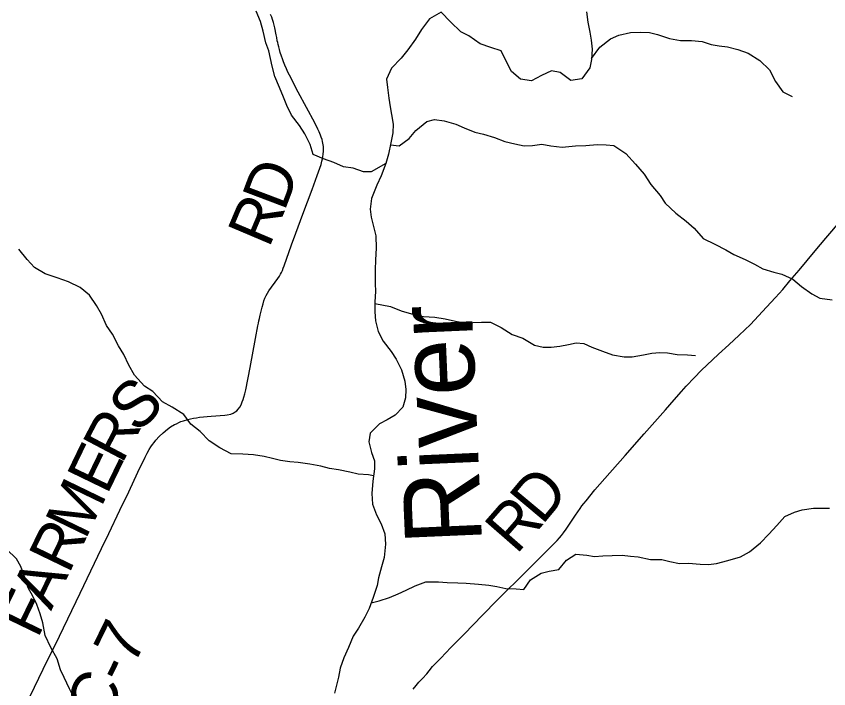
# Model space of a CAD drawing. Extents: x 0 to 1052, y -194 to 246.
# Drawn here: x 4.503 to 5.505, y 18.708 to 19.536 of the extents above; entities that cross this region are included whole.
import ezdxf

# ---------------------------------------------------------------- set-up
doc = ezdxf.new("R2010")
doc.units = 0
for name, color, linetype in [('GM_X_County_Road', 7, 'Continuous'), ('GM_X_County_Road_Text', 7, 'Continuous'), ('GM_X_County_Text', 7, 'Continuous'), ('GM_X_Major_River', 7, 'Continuous'), ('GM_X_Major_River_Text', 7, 'Continuous'), ('GM_X_Minor_River', 7, 'Continuous'), ('GM_X_Township_Road', 7, 'Continuous'), ('GM_X_Township_Road_Text', 7, 'Continuous')]:
    doc.layers.add(name, color=color, linetype=linetype)

msp = doc.modelspace()

# ---------------------------------------------------------------- linework, layer by layer
at = {"layer": 'GM_X_County_Road'}
msp.add_lwpolyline([(4.5205, 18.6985), (4.5365, 18.7315), (4.5565, 18.7722), (4.5822, 18.8253), (4.6084, 18.8803), (4.6173, 18.8987), (4.6311, 18.9273), (4.6421, 18.9502), (4.6533, 18.9744), (4.6622, 18.9929), (4.6647, 18.9976), (4.6671, 19.0022), (4.6692, 19.0054), (4.6711, 19.0083), (4.6732, 19.0109), (4.6753, 19.0136), (4.6794, 19.0181), (4.6843, 19.0228), (4.6895, 19.0271), (4.6935, 19.03), (4.6982, 19.0328), (4.7006, 19.034), (4.7037, 19.0355), (4.7063, 19.0365), (4.7094, 19.0377), (4.7147, 19.0393), (4.7179, 19.04), (4.7219, 19.0409), (4.7255, 19.0414), (4.7292, 19.042), (4.7434, 19.0433), (4.7602, 19.0444), (4.7633, 19.0448), (4.7677, 19.0459), (4.7707, 19.0471), (4.773, 19.0484), (4.775, 19.05), (4.7768, 19.0519), (4.7788, 19.0544), (4.7804, 19.0572), (4.7819, 19.0607), (4.7829, 19.0636), (4.7839, 19.0667), (4.7849, 19.0707), (4.7862, 19.0758), (4.7917, 19.1033), (4.7982, 19.1387), (4.8012, 19.1546), (4.8018, 19.1576), (4.8024, 19.1607), (4.803, 19.1637), (4.8039, 19.1676), (4.8046, 19.171), (4.8054, 19.1743), (4.8062, 19.1776), (4.8074, 19.1818), (4.8083, 19.1853), (4.8098, 19.1887), (4.8112, 19.192), (4.8129, 19.1949), (4.8146, 19.1978), (4.8258, 19.2128), (4.8276, 19.2157), (4.829, 19.2181), (4.8301, 19.2203), (4.8312, 19.2227), (4.8324, 19.2256), (4.8336, 19.2284), (4.8426, 19.2543), (4.848, 19.2688), (4.8566, 19.2921), (4.8679, 19.3223), (4.8743, 19.3398), (4.8789, 19.3534), (4.8799, 19.3572), (4.8806, 19.3601), (4.8812, 19.3632), (4.8816, 19.3657), (4.8819, 19.3701), (4.8819, 19.373), (4.8818, 19.3752), (4.8813, 19.3796), (4.8807, 19.3817), (4.8802, 19.3839), (4.8792, 19.3869), (4.8783, 19.3893), (4.8765, 19.3935), (4.8751, 19.3967), (4.8712, 19.4045), (4.8508, 19.4423), (4.8399, 19.4632), (4.8381, 19.4671), (4.8362, 19.471), (4.8343, 19.4754), (4.8326, 19.4795), (4.8313, 19.4832), (4.8301, 19.4865), (4.8287, 19.491), (4.8276, 19.4948), (4.8267, 19.4981), (4.8261, 19.5008), (4.8255, 19.5036), (4.825, 19.5056), (4.8243, 19.5096), (4.8237, 19.5129), (4.8219, 19.5215), (4.821, 19.525), (4.8202, 19.5281), (4.819, 19.5319), (4.8181, 19.5347), (4.8168, 19.5378)], dxfattribs=at)
at = {"layer": 'GM_X_Major_River'}
for points in [[(5.2059, 19.5412), (5.2075, 19.5286), (5.2103, 19.5161), (5.212, 19.5065), (5.2129, 19.4951), (5.2123, 19.4826), (5.2101, 19.4724), (5.2004, 19.4586), (5.1867, 19.4566), (5.1736, 19.4667), (5.163, 19.4684), (5.1504, 19.463), (5.1381, 19.4564), (5.1248, 19.4582), (5.1137, 19.4679), (5.1075, 19.4798), (5.1009, 19.4932), (5.0881, 19.4973), (5.0749, 19.5017), (5.0611, 19.5115), (5.0513, 19.5166), (5.0383, 19.529), (5.0268, 19.541), (5.0125, 19.5326), (5.0028, 19.5195), (4.9953, 19.5075), (4.9859, 19.4944), (4.9777, 19.4843), (4.9657, 19.472), (4.9597, 19.4585), (4.961, 19.4479), (4.9623, 19.4349), (4.964, 19.4243), (4.9657, 19.4147), (4.9677, 19.4029), (4.9675, 19.3923), (4.9649, 19.3798), (4.962, 19.3659), (4.9587, 19.3545)], [(4.9587, 19.3545), (4.9531, 19.3391), (4.9475, 19.3278), (4.9411, 19.3113), (4.9393, 19.298), (4.9406, 19.2885), (4.9434, 19.2767), (4.9466, 19.2652), (4.9467, 19.25), (4.946, 19.2356), (4.9457, 19.2235), (4.9457, 19.2068), (4.9459, 19.1966), (4.9453, 19.184), (4.9454, 19.1719), (4.9459, 19.1605), (4.9494, 19.1475), (4.9556, 19.1356), (4.9652, 19.1229), (4.9715, 19.1133), (4.978, 19.1003), (4.9823, 19.0865), (4.9836, 19.0759), (4.983, 19.066), (4.9797, 19.0543), (4.9704, 19.0446), (4.9604, 19.0388), (4.9508, 19.0337), (4.9396, 19.0225), (4.9378, 19.0115), (4.941, 18.9986), (4.9446, 18.9882), (4.9447, 18.9784), (4.9429, 18.9632), (4.9414, 18.9481), (4.9423, 18.9348), (4.9473, 18.9218), (4.9528, 18.9107), (4.9575, 18.8984), (4.9583, 18.8855), (4.9565, 18.8692), (4.9536, 18.8575), (4.9499, 18.8443), (4.9482, 18.8345), (4.9433, 18.8198), (4.9381, 18.8062), (4.9329, 18.7957), (4.925, 18.7822), (4.9184, 18.7725), (4.9128, 18.7585), (4.9068, 18.7458), (4.9024, 18.7329), (4.9006, 18.7216), (4.8956, 18.702)]]:
    msp.add_lwpolyline(points, dxfattribs=at)
at = {"layer": 'GM_X_Minor_River'}
for points in [[(4.9587, 19.3545), (4.9408, 19.344), (4.9314, 19.3441), (4.9185, 19.3488), (4.9064, 19.3505), (4.8947, 19.3556), (4.8818, 19.3603), (4.8693, 19.3654), (4.8653, 19.378), (4.859, 19.391), (4.8523, 19.4013), (4.8426, 19.414), (4.8367, 19.4258), (4.8327, 19.4361), (4.8279, 19.4479), (4.822, 19.4617), (4.8187, 19.4743), (4.8144, 19.4933), (4.8108, 19.5032), (4.8075, 19.5173), (4.8043, 19.5295), (4.7988, 19.5421)], [(5.2123, 19.4839), (5.2224, 19.4979), (5.2355, 19.508), (5.2458, 19.5124), (5.2603, 19.5156), (5.2732, 19.5162), (5.2838, 19.5157), (5.2937, 19.5133), (5.3084, 19.5085), (5.3221, 19.5061), (5.3354, 19.5059), (5.3486, 19.5046), (5.3596, 19.501), (5.3695, 19.4994), (5.3797, 19.4981), (5.3926, 19.4949), (5.4054, 19.4902), (5.4197, 19.4813), (5.4314, 19.4697), (5.4391, 19.4556), (5.4481, 19.4429), (5.4594, 19.4371)], [(4.9644, 19.3774), (4.9751, 19.3762), (4.9877, 19.3851), (4.9958, 19.3949), (5.0093, 19.4061), (5.0188, 19.4086), (5.0306, 19.407), (5.0449, 19.403), (5.0551, 19.3983), (5.0684, 19.3932), (5.079, 19.3904), (5.0926, 19.3864), (5.1054, 19.3817), (5.1179, 19.3785), (5.1293, 19.3761), (5.1396, 19.3767), (5.151, 19.3781), (5.162, 19.376), (5.176, 19.3747), (5.1923, 19.376), (5.2053, 19.3766), (5.2193, 19.3779), (5.2303, 19.3774), (5.2398, 19.3765), (5.2545, 19.3669), (5.2665, 19.3538), (5.2773, 19.3411), (5.2855, 19.3285), (5.2967, 19.3151), (5.3031, 19.3055), (5.3162, 19.2932), (5.329, 19.2835), (5.3388, 19.2747), (5.35, 19.262), (5.3643, 19.255), (5.3779, 19.248), (5.3877, 19.2425), (5.4017, 19.2363), (5.413, 19.2304), (5.4232, 19.2246), (5.4368, 19.2206), (5.4466, 19.2182), (5.4602, 19.212), (5.4711, 19.2031), (5.4839, 19.1938), (5.4937, 19.1884), (5.509, 19.1867)], [(4.9437, 18.9697), (4.9374, 18.9708), (4.9245, 18.9718), (4.9143, 18.9742), (4.9003, 18.977), (4.8893, 18.9787), (4.8787, 18.9815), (4.865, 18.9843), (4.8506, 18.986), (4.8404, 18.9869), (4.829, 18.9886), (4.8192, 18.991), (4.8089, 18.9934), (4.7957, 18.9958), (4.7824, 18.9964), (4.768, 18.997), (4.754, 19.0044), (4.7412, 19.0129), (4.73, 19.0244), (4.7183, 19.0333), (4.7097, 19.0452), (4.6954, 19.0545), (4.6834, 19.0607), (4.6714, 19.0738), (4.6612, 19.08), (4.6492, 19.0938), (4.6422, 19.106), (4.6359, 19.119), (4.6292, 19.1297), (4.6218, 19.1442), (4.6147, 19.155), (4.6084, 19.1687), (4.6021, 19.1794), (4.5936, 19.1924), (4.5819, 19.2017), (4.5676, 19.2087), (4.5536, 19.2135), (4.5388, 19.2186), (4.5256, 19.2264), (4.5167, 19.2363), (4.5066, 19.249)], [(4.9453, 19.182), (4.9645, 19.1782), (4.9777, 19.173), (4.9902, 19.1691), (5.005, 19.1662), (5.019, 19.1653), (5.0319, 19.1632), (5.0448, 19.1604), (5.0557, 19.158), (5.066, 19.1586), (5.0767, 19.1592), (5.0877, 19.1591), (5.1009, 19.1525), (5.1144, 19.1439), (5.1277, 19.1392), (5.142, 19.1307), (5.1526, 19.1283), (5.1625, 19.1281), (5.1731, 19.1295), (5.1838, 19.1317), (5.1933, 19.1334), (5.2028, 19.1329), (5.2126, 19.1282), (5.2258, 19.1231), (5.2379, 19.1188), (5.2523, 19.1163), (5.2622, 19.1162), (5.2763, 19.1187), (5.2866, 19.1208), (5.2965, 19.1215), (5.3059, 19.1213), (5.3177, 19.1193), (5.3306, 19.1187), (5.3405, 19.1179)], [(4.9408, 18.8134), (4.9505, 18.8158), (4.9631, 18.8198), (4.9738, 18.8246), (4.9838, 18.829), (4.9948, 18.8342), (5.0082, 18.8393), (5.0238, 18.8391), (5.0344, 18.8386), (5.0473, 18.8381), (5.0579, 18.8376), (5.0731, 18.8362), (5.0856, 18.8353), (5.0955, 18.8336), (5.1068, 18.8312), (5.1194, 18.8307), (5.1289, 18.8298), (5.137, 18.8418), (5.15, 18.85), (5.1599, 18.8522), (5.1721, 18.8543), (5.1814, 18.8659), (5.1929, 18.8734), (5.2065, 18.8721), (5.216, 18.8704), (5.2263, 18.8714), (5.2377, 18.8717), (5.2502, 18.8719), (5.2604, 18.871), (5.2699, 18.8701), (5.2851, 18.8669), (5.2988, 18.8667), (5.3086, 18.8643), (5.3207, 18.8619), (5.3317, 18.8621), (5.3462, 18.8608), (5.3564, 18.8606), (5.3663, 18.8617), (5.3804, 18.8653), (5.3957, 18.87), (5.4071, 18.8763), (5.4206, 18.8871), (5.4306, 18.898), (5.4406, 18.9085), (5.4506, 18.9198), (5.4625, 18.9249), (5.472, 18.9279), (5.4857, 18.93), (5.5055, 18.9301)], [(4.5752, 18.695), (4.5689, 18.7076), (4.5622, 18.7214), (4.5578, 18.7309), (4.5538, 18.7442), (4.546, 18.7584), (4.539, 18.7733), (4.5362, 18.7889), (4.5329, 18.7999), (4.5285, 18.8114), (4.5237, 18.8217), (4.5181, 18.832), (4.5134, 18.8457), (4.509, 18.858), (4.5034, 18.8675), (4.4914, 18.8794)]]:
    msp.add_lwpolyline(points, dxfattribs=at)
at = {"layer": 'GM_X_Township_Road'}
msp.add_lwpolyline([(4.9923, 18.707), (4.9961, 18.7115), (4.9996, 18.7155), (5.0039, 18.7203), (5.0092, 18.7261), (5.0121, 18.7298), (5.0162, 18.7348), (5.0208, 18.7396), (5.0272, 18.7462), (5.0318, 18.7509), (5.0395, 18.759), (5.0495, 18.7691), (5.0552, 18.7748), (5.0777, 18.798), (5.0961, 18.8165), (5.1324, 18.8529), (5.1447, 18.8652), (5.1567, 18.8769), (5.1668, 18.8869), (5.1698, 18.8902), (5.1726, 18.8933), (5.1751, 18.8963), (5.1776, 18.8995), (5.1809, 18.9039), (5.1843, 18.9089), (5.1923, 18.9215), (5.1953, 18.9256), (5.1981, 18.9296), (5.2005, 18.9327), (5.2027, 18.9355), (5.2056, 18.9391), (5.2164, 18.9524), (5.2286, 18.9665), (5.2537, 18.9949), (5.2772, 19.0214), (5.3034, 19.0512), (5.3142, 19.0632), (5.3233, 19.0735), (5.329, 19.08), (5.339, 19.091), (5.3472, 19.0995), (5.3686, 19.1195), (5.3815, 19.1311), (5.3943, 19.1429), (5.4083, 19.156), (5.428, 19.1774), (5.4388, 19.1893), (5.4479, 19.1994), (5.4568, 19.2098), (5.4681, 19.223), (5.488, 19.2467), (5.5009, 19.2625), (5.5373, 19.3049)], dxfattribs=at)

# ---------------------------------------------------------------- texts
at = {"layer": 'GM_X_County_Road_Text'}
for s, height, rotation, p in [('D', 0.0568, 69.2624, (4.8336, 19.2943)), ('R', 0.0568, 67.0469, (4.8146, 19.2492)), ('S', 0.0568, 45.1982, (4.6525, 19.0208)), ('R', 0.0568, 62.1851, (4.6333, 18.9831)), ('E', 0.0568, 64.1901, (4.6151, 18.9453)), ('M', 0.0568, 64.2168, (4.5883, 18.8898)), ('R', 0.0568, 64.2135, (4.568, 18.8478)), ('A', 0.0568, 64.2137, (4.5462, 18.8028)), ('F', 0.0568, 64.2169, (4.5295, 18.7683)), ('C-7', 0.05682, 64.0471, (4.6127, 18.6623))]:
    msp.add_text(s, height=height, rotation=rotation, dxfattribs=at).set_placement(p)
at = {"layer": 'GM_X_County_Text'}
msp.add_text('CLINTON COUNTY', height=0.189394, rotation=36.7754, dxfattribs=at).set_placement((5.3509, 18.0148))
at = {"layer": 'GM_X_Major_River_Text'}
msp.add_text('River', height=0.0947, rotation=92.4956, dxfattribs=at).set_placement((5.0774, 18.8872))
at = {"layer": 'GM_X_Township_Road_Text'}
for s, rotation, p in [('D', 50.1851, (5.1513, 18.9081)), ('R', 48.8361, (5.1196, 18.8718))]:
    msp.add_text(s, height=0.0568, rotation=rotation, dxfattribs=at).set_placement(p)

doc.saveas('drawing.dxf')
